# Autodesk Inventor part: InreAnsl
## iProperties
Shininess: 20.0
Length Units: 11269
Angle Units: 11279
Time Units: 11290
Mass Units: 11283
Length Display Precision: 3
Angle Display Precision: 2
Compacted: True
Company: Autodesk EMEA
Created: 2001-04
Part Number: InreAnsl
Material: Steel, Mild
Description: Nut
Document SubType Name: Modeling
Designer: Franz Kaltseis
Checked By: gbt
Density: 7.86
Volumn: 100.00000000000003
Area: 240.00000000000006
PropertySet Name: Model Information
Control State: 0
Master: False
Checked Out: False
Title: Mutter
Author: Franz Kaltseis
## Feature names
1. Base1
